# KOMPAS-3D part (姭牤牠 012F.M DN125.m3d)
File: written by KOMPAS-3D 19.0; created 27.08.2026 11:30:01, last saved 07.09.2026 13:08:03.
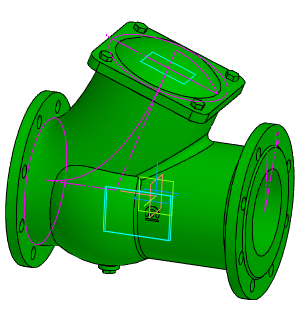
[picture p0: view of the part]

Document properties: Автор: Энергия; Полное имя файла: Z:\3.Личные\kachalov\001_3d для проектировщиков\х.х Тип 012F\012F.M\Клапан 012F.M DN125.m3d

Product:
- Part/product: (unnamed)  | designation Клапан 012F.M DN125
    Масса: 75.0763

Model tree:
1. Эскиз:1
2. Элемент вращения:1
     Угол 1 = 360
3. Эскиз:2  (with: Элемент вращения:1)
4. Перпендикулярная плоскость:1
5. Эскиз:3
6. Эскиз:12  (with: Элемент вращения:1)
7. Элемент по сечениям:1
8. Эскиз:7
9. Элемент выдавливания:2
     Расстояние 2 = 15
10. Эскиз:9  (with: Элемент выдавливания:2)
11. Элемент вращения:2
     Угол 1 = 360
12. Эскиз:10  (with: Элемент вращения:1)
13. Элемент выдавливания:3  (with: Элемент вращения:1)
     Расстояние 2 = 16
14. Массив по концентрической сетке:1  (with: Элемент выдавливания:3, Эскиз:10, Элемент вращения:1)  (8 pattern instances)
     Шаг 2 = 360
15. Эскиз:11  (with: Элемент вращения:1)
16. Элемент выдавливания:4  (with: Элемент вращения:1)
     Расстояние 2 = 16
17. Массив по концентрической сетке:2  (with: Элемент выдавливания:4, Эскиз:11, Элемент вращения:1)  (8 pattern instances)
     Шаг 2 = 360
18. Скругление:6  (with: Элемент выдавливания:2)
     Радиус = 3
19. Эскиз:13  (with: Элемент выдавливания:2)
20. Элемент выдавливания:5  (with: Элемент выдавливания:2)
     Расстояние 1 = 7; Смещение 2 = 5.5
21. Массив по концентрической сетке:3  (with: Элемент выдавливания:5, Эскиз:9, Эскиз:13, Элемент вращения:2)  (4 pattern instances)
     Шаг 2 = 360
22. Касательная плоскость:1  (with: Элемент вращения:1)
     Угол = 90
23. Смещенная плоскость:1
     Расстояние = 1
24. Эскиз:14
25. Элемент выдавливания:6  (with: Элемент вращения:1)
     Расстояние 1 = -1.00023; Расстояние 2 = 1
26. Эскиз:15  (with: Элемент вращения:1)
27. Элемент вращения:3  (with: Элемент вращения:1)
     Угол 1 = 360
28. Скругление:10  (with: Элемент вращения:3, Элемент по сечениям:1)
     Радиус = 10
29. Эскиз:16
30. Элемент выдавливания:7
     Расстояние 1 = 115
31. Эскиз:17  (with: Элемент выдавливания:7)
32. Элемент выдавливания:8
     Расстояние 1 = 6.5
33. Эскиз:18  (with: Элемент вращения:1)
34. Элемент выдавливания:9
     Расстояние 2 = 350
35. Скругление:11  (with: Элемент выдавливания:2)
     Радиус = 20
36. Скругление:12  (with: Элемент выдавливания:7)
     Радиус = 3
37. Эскиз:19  (with: Скругление:11, Элемент выдавливания:5)
38. Эскиз:20  (with: Скругление:11)

Expressions: Dn/2; D/2; D2/2; D2/2-5; 360/(2*n); 360/(n*2); D2-6; D2-5; 200/2
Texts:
  Клапан 012F.M DN125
